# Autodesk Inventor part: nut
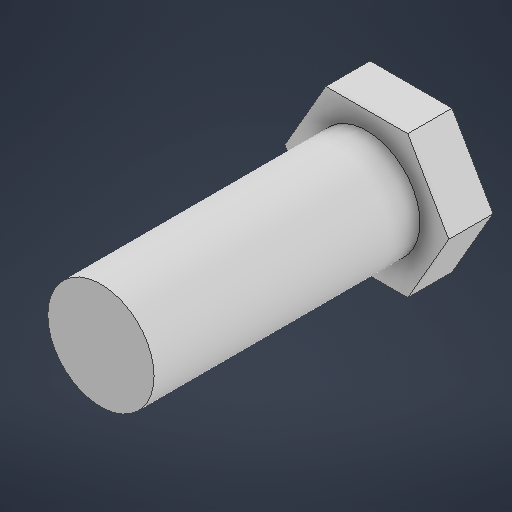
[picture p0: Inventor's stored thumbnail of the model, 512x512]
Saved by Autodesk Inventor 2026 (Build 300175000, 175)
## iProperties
Created: 2025-05
Part Number: nut
Material: Generic
Document SubType Name: Modeling
Designer: Ritul Kumari
Density: 1 g/cm^3
Appearance: Default
Author: Ritul Kumari
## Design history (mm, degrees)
node "3D Sketch1"
sketch "Sketch1"
  geometry: L1 (1.655, 0)-(1.655, 406.4); L2 (562.134, 203.2)-(444.616, -0.348); L3 (444.616, -0.348)-(209.579, -0.348); L4 (209.579, -0.348)-(92.061, 203.2); L5 (92.061, 203.2)-(209.579, 406.748); L6 (209.579, 406.748)-(444.616, 406.748); L7 (444.616, 406.748)-(562.134, 203.2); C1 r 152.4 at (327.097, 203.2); 2 further points
  constraints: 14 end point, 1 centre point, 1 coincident, 1 vertical, 13 other
  dimensions: "d0" = 406.4 distance of L1.start L1.end; "d1" = 304.8 diameter of C1
extrude "Extrusion1" new body sketch "Sketch1" distance "d2" = 127; taper "d3" = 0 deg
sketch "Sketch2"
  geometry: C1 r 152.4 at (327.097, 203.2) reference; C2 r 152.4 at (327.097, 203.2); 1 further point
  constraints: 1 centre point, 1 coincident
  dimensions: "d4" = 304.8 diameter of C2
extrude "Extrusion2" join sketch "Sketch2" distance "d5" = 762; taper "d6" = 0 deg
body "Solid1"
